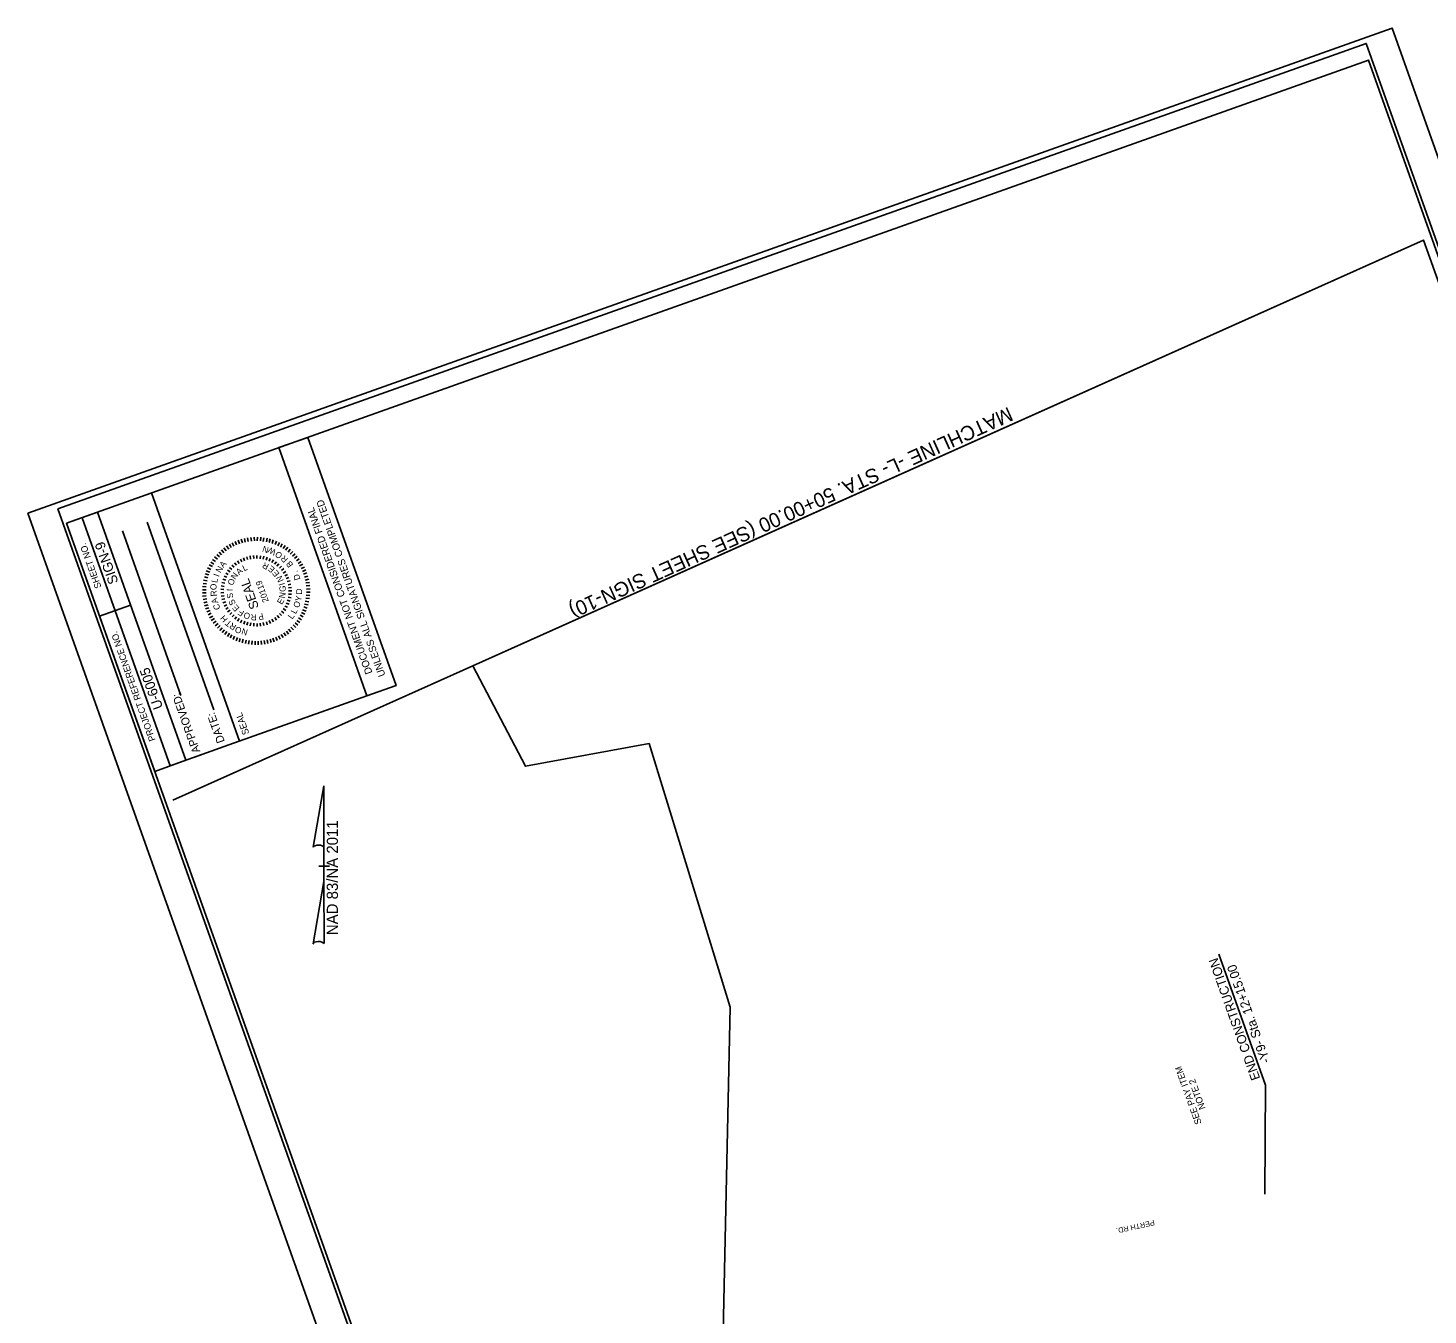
# Model space of a CAD drawing. Extents: x 1615843 to 1617444, y 901966 to 903921.
# Drawn here: x 1615843 to 1616907, y 902943 to 903921 of the extents above; entities that cross this region are included whole.
import ezdxf

# ---------------------------------------------------------------- set-up
doc = ezdxf.new("R2010")
doc.units = 0
for name, color, linetype in [('Default', 7, 'Continuous'), ('Old_Level_19', 7, 'Continuous'), ('Old_Level_20', 7, 'Continuous'), ('Prop Conc 5in Monolithic Keyed In Island', 7, 'Continuous'), ('Prop Conc Curb 9in x 12in', 7, 'Continuous'), ('Prop Conc Drive Radius Type', 7, 'Continuous'), ('Prop Dimension', 7, 'Continuous'), ('Prop Dimension Text', 7, 'Continuous'), ('Prop EOT', 7, 'Continuous'), ('Prop Lane Arrow CELL', 7, 'Continuous'), ('Prop PHM Concrete Structures Shape', 7, 'Continuous'), ('Prop Shade Medium', 7, 'Continuous'), ('Scratch_Level_2', 7, 'Continuous'), ('Scratch_Level_6', 7, 'Continuous'), ('Scratch_Level_7', 7, 'Continuous')]:
    doc.layers.add(name, color=color, linetype=linetype)

msp = doc.modelspace()

# ---------------------------------------------------------------- linework, layer by layer
at = {"layer": 'Default'}
for p, q in [((1616002.8, 903531.8), (1616003.7, 903529.1)), ((1616005.1, 903532.5), (1616005.9, 903529.8)), ((1616007.5, 903533.1), (1616008.1, 903530.4)), ((1616009.9, 903533.6), (1616010.4, 903530.8)), ((1616012.4, 903533.9), (1616012.7, 903531.1)), ((1616014.8, 903534.1), (1616015, 903531.3)), ((1616017.3, 903534.1), (1616017.2, 903531.3)), ((1616019.8, 903534), (1616019.6, 903531.2)), ((1616022.2, 903533.7), (1616021.8, 903530.9)), ((1616024.7, 903533.3), (1616024.1, 903530.5)), ((1616027.1, 903532.7), (1616026.3, 903530)), ((1616029.4, 903532), (1616028.5, 903529.3)), ((1615986.4, 903521), (1615988.5, 903519.1)), ((1615988.2, 903522.8), (1615990.1, 903520.7)), ((1615990, 903524.4), (1615991.8, 903522.3)), ((1615991.9, 903526), (1615993.6, 903523.7)), ((1615993.9, 903527.4), (1615995.5, 903525)), ((1615996, 903528.7), (1615997.4, 903526.3)), ((1615998.2, 903529.8), (1615999.5, 903527.3)), ((1616000.5, 903530.9), (1616001.5, 903528.3)), ((1616031.7, 903531.1), (1616030.7, 903528.5)), ((1616034, 903530.1), (1616032.8, 903527.6)), ((1616036.2, 903529), (1616034.9, 903526.6)), ((1616038.3, 903527.7), (1616036.8, 903525.4)), ((1616040.4, 903526.4), (1616038.7, 903524.1)), ((1616042.3, 903524.9), (1616040.6, 903522.7)), ((1616044.2, 903523.2), (1616042.3, 903521.2)), ((1616045.9, 903521.5), (1616043.9, 903519.6)), ((1615979.5, 903510.8), (1615982, 903509.6)), ((1615980.6, 903513), (1615983.1, 903511.7)), ((1615981.9, 903515.1), (1615984.3, 903513.6)), ((1615983.3, 903517.2), (1615985.6, 903515.6)), ((1615984.8, 903519.1), (1615987, 903517.4)), ((1615996.2, 903511), (1615998, 903509.5)), ((1615998, 903512.9), (1615999.6, 903511.2)), ((1616000, 903514.6), (1616001.4, 903512.8)), ((1616002.2, 903516.1), (1616003.4, 903514.1)), ((1616004.4, 903517.4), (1616005.5, 903515.3)), ((1616006.8, 903518.4), (1616007.6, 903516.2)), ((1616009.3, 903519.2), (1616009.9, 903517)), ((1616012.1, 903517.5), (1616011.7, 903519.8)), ((1616014.4, 903520.1), (1616014.6, 903517.8)), ((1616017, 903520.2), (1616017, 903517.8)), ((1616019.6, 903520), (1616019.3, 903517.7)), ((1616022.2, 903519.6), (1616021.7, 903517.3)), ((1616024.7, 903518.9), (1616024, 903516.7)), ((1616027.1, 903518), (1616026.2, 903515.8)), ((1616029.5, 903516.8), (1616028.3, 903514.8)), ((1616031.7, 903515.4), (1616030.4, 903513.5)), ((1616033.7, 903513.9), (1616032.2, 903512.1)), ((1616035.7, 903512.1), (1616034, 903510.5)), ((1616047.6, 903519.7), (1616045.5, 903517.9)), ((1616049.1, 903517.7), (1616046.9, 903516.1)), ((1616050.6, 903515.7), (1616048.2, 903514.2)), ((1616051.9, 903513.6), (1616049.4, 903512.2)), ((1616053, 903511.4), (1616050.5, 903510.2)), ((1615976.4, 903501.5), (1615979.1, 903500.9)), ((1615977, 903503.9), (1615979.6, 903503.2)), ((1615977.7, 903506.2), (1615980.3, 903505.4)), ((1615978.5, 903508.6), (1615981.1, 903507.5)), ((1615991, 903502.1), (1615993.2, 903501.4)), ((1615992, 903504.5), (1615994.1, 903503.6)), ((1615993.2, 903506.8), (1615995.2, 903505.7)), ((1615994.6, 903509), (1615996.5, 903507.7)), ((1616037.4, 903510.2), (1616035.6, 903508.7)), ((1616038.9, 903508), (1616037, 903506.8)), ((1616040.2, 903505.8), (1616038.2, 903504.7)), ((1616041.3, 903503.5), (1616039.2, 903502.6)), ((1616042.2, 903501), (1616040, 903500.3)), ((1616054, 903509.2), (1616051.5, 903508.1)), ((1616054.9, 903506.9), (1616052.3, 903506)), ((1616055.7, 903504.5), (1616053, 903503.8)), ((1616056.3, 903502.1), (1616053.6, 903501.5)), ((1616056.8, 903499.7), (1616054, 903499.3)), ((1615975.6, 903494.1), (1615978.3, 903494.1)), ((1615975.6, 903491.7), (1615978.4, 903491.8)), ((1615975.7, 903496.6), (1615978.5, 903496.4)), ((1615975.7, 903489.2), (1615978.5, 903489.5)), ((1615976, 903499), (1615978.7, 903498.6)), ((1615989.5, 903494.5), (1615991.8, 903494.4)), ((1615989.5, 903491.9), (1615991.8, 903492)), ((1615989.8, 903497.1), (1615992, 903496.7)), ((1615989.8, 903489.3), (1615992.1, 903489.6)), ((1615990.2, 903499.6), (1615992.5, 903499.1)), ((1616042.8, 903498.5), (1616040.6, 903498)), ((1616040.9, 903495.7), (1616043.2, 903495.9)), ((1616043.2, 903490.7), (1616040.9, 903490.9)), ((1616043.4, 903493.3), (1616041, 903493.3)), ((1616057.1, 903497.3), (1616054.3, 903497)), ((1616057.2, 903489.9), (1616054.4, 903490.1)), ((1616057.3, 903494.8), (1616054.5, 903494.7)), ((1616057.3, 903492.3), (1616054.5, 903492.4)), ((1615976.1, 903486.7), (1615978.8, 903487.2)), ((1615976.5, 903484.3), (1615979.2, 903484.9)), ((1615977.1, 903481.9), (1615979.8, 903482.7)), ((1615977.9, 903479.6), (1615980.5, 903480.5)), ((1615990.3, 903486.7), (1615992.5, 903487.3)), ((1615991, 903484.2), (1615993.2, 903485)), ((1615993.2, 903485), (1615991, 903484.2)), ((1615992, 903481.8), (1615994.1, 903482.8)), ((1615993.2, 903479.5), (1615995.2, 903480.7)), ((1615994.7, 903477.3), (1615996.5, 903478.7)), ((1616039, 903478.5), (1616037, 903479.8)), ((1616040.3, 903480.8), (1616038.2, 903481.8)), ((1616041.4, 903483.1), (1616039.2, 903484)), ((1616042.3, 903485.6), (1616040, 903486.2)), ((1616042.9, 903488.1), (1616040.6, 903488.6)), ((1616054.3, 903477.9), (1616051.7, 903479)), ((1616055.2, 903480.2), (1616052.5, 903481.1)), ((1616055.9, 903482.6), (1616053.2, 903483.3)), ((1616056.5, 903485), (1616053.7, 903485.6)), ((1616056.9, 903487.4), (1616054.1, 903487.8)), ((1615978.8, 903477.3), (1615981.4, 903478.4)), ((1615979.8, 903475), (1615982.3, 903476.3)), ((1615981, 903472.9), (1615983.4, 903474.2)), ((1615982.3, 903470.8), (1615984.6, 903472.3)), ((1615983.7, 903468.7), (1615985.9, 903470.4)), ((1615985.2, 903466.8), (1615987.4, 903468.6)), ((1615996.3, 903475.3), (1615998, 903476.9)), ((1615998.1, 903473.5), (1615999.7, 903475.2)), ((1616000.1, 903471.8), (1616001.5, 903473.6)), ((1616002.3, 903470.3), (1616003.5, 903472.3)), ((1616004.5, 903469.1), (1616005.6, 903471.1)), ((1616006.9, 903468), (1616007.7, 903470.2)), ((1616009.4, 903467.2), (1616010, 903469.5)), ((1616011.9, 903466.7), (1616012.3, 903469)), ((1616014.5, 903466.4), (1616014.7, 903468.7)), ((1616017.1, 903466.3), (1616017.1, 903468.6)), ((1616019.7, 903466.5), (1616019.4, 903468.8)), ((1616022.3, 903466.9), (1616021.8, 903469.2)), ((1616024.8, 903467.6), (1616024.1, 903469.8)), ((1616027.2, 903468.6), (1616026.3, 903470.7)), ((1616029.6, 903469.7), (1616028.4, 903471.7)), ((1616031.8, 903471.1), (1616030.5, 903473)), ((1616033.8, 903472.7), (1616032.3, 903474.5)), ((1616035.7, 903474.5), (1616034.1, 903476.1)), ((1616037.5, 903476.4), (1616035.7, 903477.9)), ((1616048, 903467.3), (1616045.9, 903469.1)), ((1616049.5, 903469.3), (1616047.3, 903470.9)), ((1616050.9, 903471.3), (1616048.6, 903472.8)), ((1616052.2, 903473.5), (1616049.8, 903474.8)), ((1616053.3, 903475.6), (1616050.8, 903476.8)), ((1615986.9, 903465), (1615988.9, 903466.9)), ((1615988.7, 903463.2), (1615990.5, 903465.3)), ((1615990.5, 903461.6), (1615992.3, 903463.8)), ((1615992.5, 903460.1), (1615994.1, 903462.4)), ((1615994.5, 903458.7), (1615996, 903461.1)), ((1615996.6, 903457.5), (1615998, 903459.9)), ((1615998.8, 903456.3), (1616000, 903458.8)), ((1616001.1, 903455.3), (1616002.1, 903457.9)), ((1616030.1, 903454.7), (1616029.1, 903457.3)), ((1616032.4, 903455.6), (1616031.3, 903458.2)), ((1616034.6, 903456.6), (1616033.4, 903459.1)), ((1616036.8, 903457.8), (1616035.4, 903460.2)), ((1616038.9, 903459.1), (1616037.4, 903461.4)), ((1616040.9, 903460.5), (1616039.3, 903462.7)), ((1616042.8, 903462.1), (1616041, 903464.2)), ((1616044.7, 903463.7), (1616042.8, 903465.7)), ((1616046.4, 903465.5), (1616044.4, 903467.4)), ((1616003.4, 903454.5), (1616004.3, 903457.1)), ((1616005.8, 903453.8), (1616006.5, 903456.5)), ((1616008.2, 903453.2), (1616008.7, 903455.9)), ((1616010.6, 903452.8), (1616011, 903455.5)), ((1616013.1, 903452.5), (1616013.3, 903455.3)), ((1616015.5, 903452.4), (1616015.6, 903455.2)), ((1616018, 903452.4), (1616017.9, 903455.2)), ((1616020.5, 903452.6), (1616020.2, 903455.3)), ((1616022.9, 903452.9), (1616022.5, 903455.6)), ((1616025.3, 903453.3), (1616024.7, 903456.1)), ((1616027.7, 903454), (1616027, 903456.6))]:
    msp.add_line(p, q, dxfattribs=at)
at = {"layer": 'Old_Level_20'}
msp.add_lwpolyline([(1616920.6, 902383), (1616427.5, 902361.6), (1616381.8, 902566.8), (1616370.3, 902895), (1616376.6, 903177.1), (1616314.9, 903377.3), (1616220.9, 903360.1), (1616181.1, 903436.4), (1616369.2, 903520.6), (1616903.3, 903759.8), (1617120.2, 903154.3), (1617263.4, 902747.8), (1617083.5, 902390)], close=True, dxfattribs=at)
at = {"layer": 'Prop Conc 5in Monolithic Keyed In Island'}
for p, q in [((1616033.5, 903602.1), (1616100.5, 903413.6)), ((1616003.8, 903379.2), (1615936.8, 903567.7)), ((1616100.5, 903413.6), (1615995.6, 903376.3)), ((1615995.6, 903376.3), (1615951.1, 903360.4))]:
    msp.add_line(p, q, dxfattribs=at)
at = {"layer": 'Prop Conc Curb 9in x 12in'}
for p, q in [((1616783.1, 903117.9), (1616747.8, 903217.3)), ((1616782.7, 903035.1), (1616783.1, 903117.9))]:
    msp.add_line(p, q, dxfattribs=at)
at = {"layer": 'Prop Dimension'}
msp.add_lwpolyline([(1616100.5, 903413.6), (1616033.5, 903602.1), (1616055.7, 903609.9), (1616122.7, 903421.4)], close=True, dxfattribs=at)
at = {"layer": 'Prop Dimension Text'}
msp.add_line((1615953.1, 903334.3), (1616903.3, 903759.8), dxfattribs=at)
at = {"layer": 'Prop EOT'}
for p, q in [((1616059.7, 903298.7), (1616067.9, 903345.1)), ((1616067.9, 903345.1), (1616067.9, 903345.1)), ((1616067.9, 903345.1), (1616067.9, 903345.1)), ((1616067.9, 903345.1), (1616067.9, 903297.3)), ((1616067.9, 903272.5), (1616067.9, 903298.7)), ((1616067.9, 903297.3), (1616067.9, 903298.6)), ((1616067.5, 903284.1), (1616063.9, 903284.1)), ((1616063.9, 903284.1), (1616063.9, 903284.1)), ((1616064, 903284.1), (1616072, 903284.1)), ((1616067.9, 903272.5), (1616059.6, 903225.2)), ((1616068, 903225.4), (1616067.9, 903272.5))]:
    msp.add_line(p, q, dxfattribs=at)
for centre, start_param, end_param in [((1616063.8, 903298.2), 0.216388, 2.908219), ((1616063.8, 903225), 0.201328, 3.141593)]:
    msp.add_ellipse(centre, major_axis=(4.23, -0.03), ratio=0.461098, start_param=start_param, end_param=end_param, dxfattribs=at)
at = {"layer": 'Prop PHM Concrete Structures Shape'}
for p, q in [((1615962.9, 903364.6), (1615895.9, 903553.1)), ((1615962.9, 903364.6), (1615895.9, 903553.1)), ((1615951.1, 903360.4), (1615884.1, 903548.9)), ((1615897.4, 903474.1), (1615921, 903482.5)), ((1615962.9, 903364.6), (1615974.7, 903368.8))]:
    msp.add_line(p, q, dxfattribs=at)
for points in [[(1615872.3, 903544.7), (1616374.7, 902131.4), (1617364.1, 902483.1), (1616861.6, 903896.5)], [(1615939.3, 903356.2), (1615872.3, 903544.7), (1615895.9, 903553.1), (1615962.9, 903364.6)]]:
    msp.add_lwpolyline(points, close=True, dxfattribs=at)
at = {"layer": 'Prop Shade Medium'}
msp.add_lwpolyline([(1615843, 903552.4), (1616407.1, 901965.7), (1617443.6, 902334.1), (1616879.5, 903920.8)], close=True, dxfattribs=at)
at = {"layer": 'Scratch_Level_2'}
msp.add_lwpolyline([(1615865.7, 903555.7), (1616423.9, 901985.4), (1617418.1, 902338.9), (1616859.8, 903909.1)], close=True, dxfattribs=at)
at = {"layer": 'Scratch_Level_6'}
for p, q in [((1615984.1, 903403), (1615933.5, 903545.5)), ((1615959.1, 903413.9), (1615914.7, 903538.9))]:
    msp.add_line(p, q, dxfattribs=at)

# ---------------------------------------------------------------- texts
at = {"layer": 'Default'}
for s, height, rotation, p in [('N', 4.64, 161.7247, (1616026.3, 903526.2)), ('W', 4.64, 152.8421, (1616032, 903524.1)), ('O', 4.64, 143.9595, (1616036.8, 903521)), ('N', 4.64, 59.8023, (1615989.3, 903506.5)), ('A', 4.64, 50.0348, (1615991.5, 903510.5)), ('L', 4.64, 25.3883, (1616007.2, 903508.1)), ('R', 4.64, 154.0826, (1616026.5, 903513.3)), ('E', 4.64, 140.3115, (1616031, 903510.2)), ('R', 4.64, 135.1368, (1616041, 903517.5)), ('B', 4.64, 126.1343, (1616044.8, 903513.2)), ('L', 4.64, 78.6722, (1615986.7, 903499.1)), ('I', 4.64, 69.0968, (1615988, 903503.6)), ('O', 4.64, 71.2771, (1615998.9, 903497.1)), ('N', 4.64, 55.9808, (1616000.6, 903501.5)), ('A', 4.64, 40.6846, (1616003.4, 903505.2)), ('SEAL', 6.97, 109.5177, (1616018.6, 903480.8)), ('20119', 4.64, 109.5177, (1616026, 903485.4)), ('E', 4.64, 130.3256, (1616034.4, 903506.4)), ('N', 4.64, 114.9335, (1616037.4, 903501.2)), ('D', 4.64, 105.6076, (1616050.1, 903502.1)), ('.', 4.64, 113.35, (1616048.2, 903507.6)), ('O', 4.64, 91.8085, (1615986.3, 903494)), ('R', 4.64, 94.8653, (1615986.6, 903489.3)), ('I', 4.64, 86.5733, (1615998.5, 903493)), ('S', 4.64, 101.8695, (1615999.2, 903488)), ('I', 4.64, 107.3039, (1616038.3, 903498.2)), ('N', 4.64, 80.4428, (1616038.2, 903487.4)), ('G', 4.64, 89.2091, (1616038.7, 903492.5)), ('Y', 4.64, 78.8398, (1616050.4, 903485)), ('D', 4.64, 87.8123, (1616051.2, 903490.5)), ('A', 4.64, 106.8746, (1615987.6, 903484.4)), ('C', 4.64, 106.8746, (1615989.2, 903479.6)), ('S', 4.64, 117.1658, (1616001.1, 903483.7)), ('E', 4.64, 132.462, (1616004, 903480.2)), ('E', 4.64, 59.5878, (1616035.9, 903482.5)), ('L', 4.64, 61.5245, (1616046.4, 903475.4)), ('O', 4.64, 70.1672, (1616048.7, 903480)), ('H', 4.64, 130.5853, (1615995.1, 903471.9)), ('T', 4.64, 140.0173, (1615998.2, 903469.1)), ('R', 4.64, 148.1782, (1616001.7, 903467)), ('F', 4.64, 147.7583, (1616007.7, 903477.5)), ('O', 4.64, 163.0545, (1616012.3, 903475.9)), ('R', 4.64, 178.3508, (1616016.8, 903475.5)), ('P', 4.64, 193.647, (1616021.4, 903476.4)), ('L', 4.64, 53.4527, (1616043.7, 903471.4)), ('O', 4.64, 161.235, (1616005.8, 903464.9)), ('N', 4.64, 163.1944, (1616010.4, 903463.7)), ('SEE PAY ITEM', 5, 109.8068, (1616734.8, 903089)), ('NOTE 2', 5, 109.8068, (1616737.7, 903100.3))]:
    msp.add_text(s, height=height, rotation=rotation, dxfattribs=at).set_placement(p)
at = {"layer": 'Old_Level_19'}
for s, p in [('SIGN-9', (1615911.8, 903499.9)), ('U-6005', (1615945.7, 903404.8))]:
    msp.add_text(s, height=7.5, rotation=109.5707, dxfattribs=at).set_placement(p)
at = {"layer": 'Prop Conc Curb 9in x 12in'}
for s, p in [('END CONSTRUCTION', (1616779.3, 903123)), ('-Y9- Sta. 12+15.00', (1616786.8, 903135.9))]:
    msp.add_text(s, height=7, rotation=109.5707, dxfattribs=at).set_placement(p)
at = {"layer": 'Prop Conc Drive Radius Type'}
msp.add_text('PERTH RD.', height=4, rotation=192.4863, dxfattribs=at).set_placement((1616698.5, 903015.5))
at = {"layer": 'Prop Dimension'}
for s, p in [('DOCUMENT NOT CONSIDERED FINAL', (1616104.8, 903431.1)), ('UNLESS ALL SIGNATURES COMPLETED', (1616114.7, 903429.2))]:
    msp.add_text(s, height=5.498, rotation=109.5707, dxfattribs=at).set_placement(p)
at = {"layer": 'Prop EOT'}
msp.add_text('NAD 83/NA 2011', height=8.5, rotation=90, dxfattribs=at).set_placement((1616078.5, 903231.8))
at = {"layer": 'Prop Lane Arrow CELL'}
msp.add_text('MATCHLINE -L- STA. 50+00.00 (SEE SHEET SIGN-10)', height=11, rotation=204.2818, dxfattribs=at).set_placement((1616588, 903633.3))
at = {"layer": 'Prop PHM Concrete Structures Shape'}
for s, p in [('SHEET NO.', (1615898.9, 903496.1)), ('PROJECT REFERENCE NO.', (1615940, 903380.1))]:
    msp.add_text(s, height=5, rotation=109.5707, dxfattribs=at).set_placement(p)
at = {"layer": 'Scratch_Level_6'}
msp.add_text('SEAL', height=5.09, rotation=109.5656, dxfattribs=at).set_placement((1616011.2, 903385))
at = {"layer": 'Scratch_Level_7'}
for s, p in [('APPROVED:', (1615974, 903371.3)), ('DATE:', (1615992.6, 903378.9))]:
    msp.add_text(s, height=6.11, rotation=109.5656, dxfattribs=at).set_placement(p)

doc.saveas('drawing.dxf')
